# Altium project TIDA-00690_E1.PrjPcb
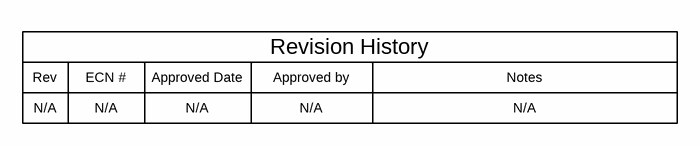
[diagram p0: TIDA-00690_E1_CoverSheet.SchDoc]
CopyrightYear: 2016; PCB_Layout: Who did the Layout?; PCB_Rev: E1; PRJ_Customer: Public Release; PRJ_Engineer: Enter name of project lead; PRJ_Number: TIDA-00690; PRJ_Title: Power for Wireless Switch; SCH_Rev: E1; TechSupport: http://www.ti.com/support; TID: TIDA-00690
2 sheets, 30 parts. Net scope: global (net labels, ports and power ports of the same name join across sheets).
Board file: TIDA-00690_E1_PCB.PcbDoc
Sheets:
  TIDA-00690_E1_CoverSheet.SchDoc
  TIDA-00690_E1_BlankSheet.SchDoc

## Sheet TIDA-00690_E1_CoverSheet.SchDoc
size 431 x 279 mm; Date: Not shown in title block; ApprovedBy: Not shown in title block; CheckedBy: Not shown in title block; Author: Not shown in title block; CompanyName: Not shown in title block; Engineer: Not shown in title block; Organization: Not shown in title block; Address1: Not shown in title block; Address2: Not shown in title block; Address3: Not shown in title block; Address4: Not shown in title block; DocumentNumber: 1; Revision: Use project parameter SCH_Rev; SheetNumber: 1; SheetTotal: 3; PageSetup: Record=PageOptions¦CenterHorizontal=True¦CenterVertical=True¦PrintScale=1.00¦XCorrection=1.00¦YCorrection=1.00¦PrintKind=0¦BorderSize=5000000¦LeftOffset=0¦BottomOffset=0¦Orientation=2¦PaperLength=1000¦PaperWidth=1000¦Scale=100¦PaperSource=15¦PrintQuality=600¦MediaType=1¦DitherType=10¦PaperKind=Letter¦PrintScaleMode=1

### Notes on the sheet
- Rev
- N/A
- ECN #
- Approved Date
- Approved by
- Revision History
- Notes

## Sheet TIDA-00690_E1_BlankSheet.SchDoc
size 431 x 279 mm; Date: Not shown in title block; ApprovedBy: Not shown in title block; CheckedBy: Not shown in title block; Author: Not shown in title block; CompanyName: Not shown in title block; Engineer: Not shown in title block; Organization: Not shown in title block; Address1: Not shown in title block; Address2: Not shown in title block; Address3: Not shown in title block; Address4: Not shown in title block; DocumentNumber: 1; Revision: Use project parameter SCH_Rev; SheetNumber: 2; SheetTotal: 3; PageSetup: Record=PageOptions¦CenterHorizontal=True¦CenterVertical=True¦PrintScale=1.00¦XCorrection=1.00¦YCorrection=1.00¦PrintKind=0¦BorderSize=5000000¦LeftOffset=0¦BottomOffset=0¦Orientation=2¦PaperLength=1000¦PaperWidth=1000¦Scale=100¦PaperSource=15¦PrintQuality=600¦MediaType=1¦DitherType=10¦PaperKind=Letter¦PrintScaleMode=1
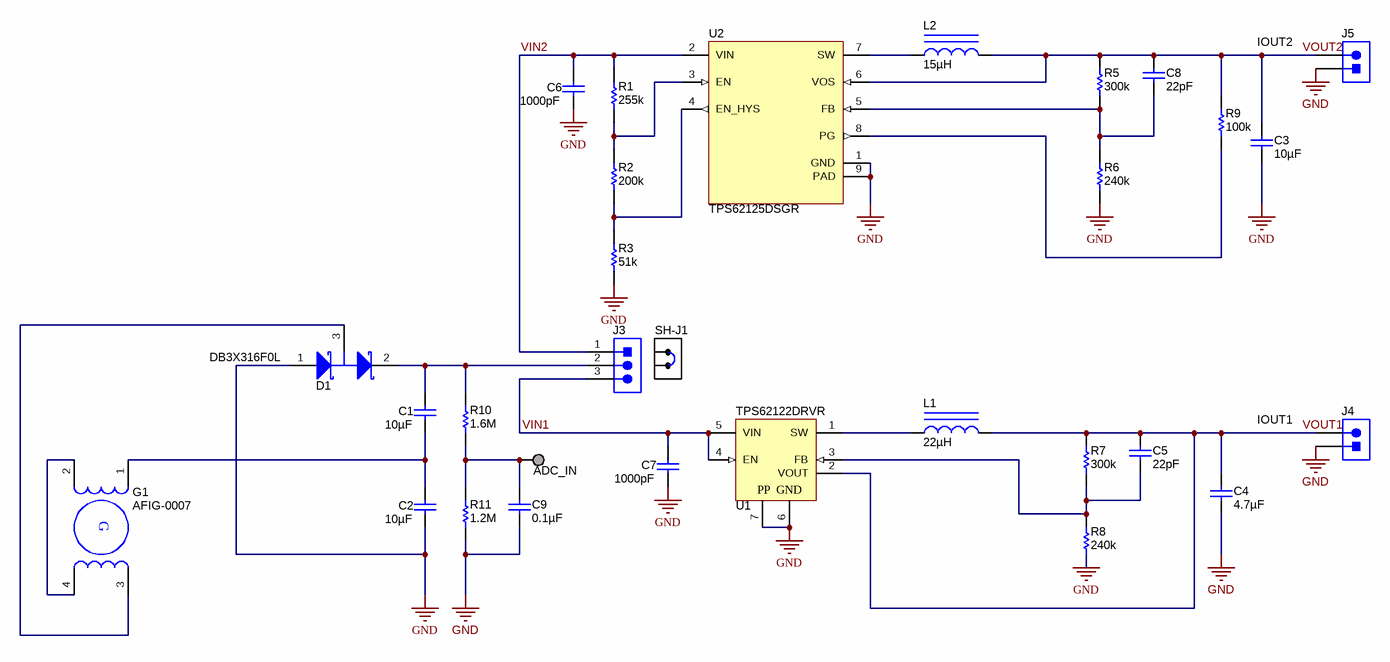
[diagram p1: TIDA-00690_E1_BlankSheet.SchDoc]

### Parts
ADC_IN  TESTPOINT  [TP_H045P075]  (value not drawn)  (no BOM)
C1  ValueDisplayed: 10µF  [0805_HV]  (hidden comment: GRM21BR61E106MA73)
C2  ValueDisplayed: 10µF  [0805_HV]  (hidden comment: GRM21BR61E106MA73)
C3  ValueDisplayed: 10µF  [0805_HV]  (hidden comment: GRM21BR61C106KE15L)
C4  ValueDisplayed: 4.7µF  [0603]  (hidden comment: GRM188R60J475KE19D)
C5  ValueDisplayed: 22pF  [0603]  (hidden comment: GRM1885C1H220JA01D)
C6  ValueDisplayed: 1000pF  [1206]  (hidden comment: GRM3195C1H102JA01D)
C7  ValueDisplayed: 1000pF  [1206]  (hidden comment: GRM3195C1H102JA01D)
C8  ValueDisplayed: 22pF  [0603]  (hidden comment: GRM1885C1H220JA01D)
C9  ValueDisplayed: 0.1µF  [0603]  (hidden comment: GRM188R71E104KA01D)
D1  DB3X316F0L  [SOT-23]
G1  AFIG-0007  [Cherry_AFIG-0007]
J3  61300311121  [WURTH_61300311121]  (value not drawn)
J4  61300211121  [WURTH_61300211121]  (value not drawn)
J5  61300211121  [WURTH_61300211121]  (value not drawn)
L1  ValueDisplayed: 22µH  [LQH3NP_G0]  (hidden comment: LQH3NPN220NG0)
L2  ValueDisplayed: 15µH  [LPS3314]  (hidden comment: LPS3314-153MLB)
R1  ValueDisplayed: 255k  [0603]  (hidden comment: CRCW0603255KFKEA)
R2  ValueDisplayed: 200k  [0603]  (hidden comment: CRCW0603200KFKEA)
R3  ValueDisplayed: 51k  [0603]  (hidden comment: RC0603JR-0751KL)
R5  ValueDisplayed: 300k  [0603]  (hidden comment: CRCW0603300KFKEA)
R6  ValueDisplayed: 240k  [0603]  (hidden comment: RC0603FR-07240KL)
R7  ValueDisplayed: 300k  [0603]  (hidden comment: CRCW0603300KFKEA)
R8  ValueDisplayed: 240k  [0603]  (hidden comment: RC0603FR-07240KL)
R9  ValueDisplayed: 100k  [0603]  (hidden comment: CRCW0603100KJNEA)
R10  ValueDisplayed: 1.6M  [0805_HV]  (hidden comment: CRCW08051M60JNEA)
R11  ValueDisplayed: 1.2M  [0805_HV]  (hidden comment: CRCW08051M20JNEA)
SH-J1  969102-0000-DA  [SNT-100-BK-G]  (value not drawn)
U1  TPS62122DRVR  [DRV0006A]
U2  TPS62125DSGR  [DSG0008A]

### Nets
GND: C2.2 C3.2 C4.2 C6.2 C7.2 C9.2 D1.1(A) J4.1 J5.1 R3.1 R6.1 R8.1 R11.1 U1.6(GND) U1.7(EP) U2.1(GND) U2.9(PAD)
VIN1: C7.1 J3.3 U1.4(EN) U1.5(VIN)
VIN2: C6.1 J3.1 R1.2 U2.2(VIN)
VOUT1: C4.1 C5.1 J4.2 L1.2 R7.2 U1.2(VOUT)
VOUT2: C3.1 C8.1 J5.2 L2.2 R5.2 R9.2 U2.6(VOS)
NetADC_IN_1: ADC_IN.1 C9.1 R10.1 R11.2
NetC1_1: C1.1 D1.2(K) J3.2 R10.2
NetC1_2: C1.2 C2.1 G1.1
NetC5_2: C5.2 R7.1 R8.2 U1.3(FB)
NetC8_2: C8.2 R5.1 R6.2 U2.5(FB)
NetD1_3: D1.3(C) G1.3
NetG1_2: G1.2 G1.4
NetL1_1: L1.1 U1.1(SW)
NetL2_1: L2.1 U2.7(SW)
NetR1_1: R1.1 R2.2 U2.3(EN)
NetR2_1: R2.1 R3.2 U2.4(EN_HYS)
NetR9_1: R9.1 U2.8(PG)

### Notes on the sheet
- IOUT2
- IOUT1

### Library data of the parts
ADC_IN = TP_H0.45P0.75: Manufacturer: Texas Instruments; CompType: Pad
C1 C2 = GRM21BR61E106MA73: CAP, CERM, 10 µF, 25 V, +/- 20%, X5R, 0805; Manufacturer: MuRata; Polarized: N; CompType: Capacitor; Value: 10uF; U/M: EA; Cap_F: 0.00001; Tolerance_%: 20; Value1: Unknown; VDC_V: 25; Value2: 25V; TaMin_C: -55; TaMax_C: 85; Cap_Case: 0805; SizeArea_mm2: 2.5; SizeAreaWB_mm2: 6.75; SizeX_mm: 2; SizeY_mm: 1.25; SizeZ_mm: 1.45; AEC Category: Q200
C3 = GRM21BR61C106KE15L: CAP, CERM, 10 µF, 16 V, +/- 10%, X5R, 0805; Manufacturer: MuRata; Polarized: N; CompType: Capacitor; Value: 10uF; U/M: EA; Cap_F: 0.00001; Tolerance_%: 10; ESR_ohm: 0.008; Value1: 0.008 ohm; VDC_V: 16; Value2: 16V; TaMin_C: -55; TaMax_C: 85; Cap_Case: 0805; SizeArea_mm2: 2.5; SizeAreaWB_mm2: 6.75; SizeX_mm: 2; SizeY_mm: 1.25; SizeZ_mm: 1.45; AEC Category: Q200
C4 = GRM188R60J475KE19D: CAP, CERM, 4.7 µF, 6.3 V, +/- 10%, X5R, 0603; Manufacturer: MuRata; Polarized: N; CompType: Capacitor; Value: 4.7uF; U/M: EA; Cap_F: 0.0000047; Tolerance_%: 10; ESR_ohm: 0.005; Value1: 0.005 ohm; VDC_V: 6.3; Value2: 6.3V; IRMS_A: 2; TaMin_C: -55; TaMax_C: 85; SizeArea_mm2: 1.28; SizeAreaWB_mm2: 4.68; SizeX_mm: 1.6; SizeY_mm: 0.8; SizeZ_mm: 1; AEC Category: Q200
C5 C8 = GRM1885C1H220JA01D: CAP, CERM, 22 pF, 50 V, +/- 5%, C0G/NP0, 0603; Manufacturer: MuRata; Polarized: N; CompType: Capacitor; Value: 22pF; U/M: EA; Cap_F: 0.000000000022; Tolerance_%: 5; Value1: Unknown; VDC_V: 50; Value2: 50V; TaMin_C: -55; TaMax_C: 125; SizeArea_mm2: 1.28; SizeAreaWB_mm2: 4.68; SizeX_mm: 1.6; SizeY_mm: 0.8; SizeZ_mm: 1; AEC Category: Q200
C6 C7 = GRM3195C1H102JA01D: CAP, CERM, 1000 pF, 50 V, +/- 5%, C0G/NP0, 1206; Manufacturer: MuRata; Polarized: N; CompType: Capacitor; Value: 1000pF; U/M: EA; Cap_F: 0.000000001; Tolerance_%: 5; Value1: Unknown; VDC_V: 50; Value2: 50V; TaMin_C: -55; TaMax_C: 125; SizeArea_mm2: 5.12; SizeAreaWB_mm2: 10.92; SizeX_mm: 3.2; SizeY_mm: 1.6; SizeZ_mm: 1.35; AEC Category: Q200
C9 = GRM188R71E104KA01D: CAP, CERM, 0.1 µF, 25 V, +/- 10%, X7R, 0603; Manufacturer: MuRata; Polarized: N; CompType: Capacitor; Value: 0.1uF; U/M: EA; Cap_F: 0.0000001; Tolerance_%: 10; Value1: Unknown; VDC_V: 25; Value2: 25V; TaMin_C: -55; TaMax_C: 125; SizeArea_mm2: 1.28; SizeAreaWB_mm2: 4.68; SizeX_mm: 1.6; SizeY_mm: 0.8; SizeZ_mm: 1; AEC Category: Q200
D1 = DB3X316F0L: Diode, Schottky, 30 V, 0.1 A, SOT-23; Manufacturer: Panasonic; SymbolCreator: Altium; U/M: EA; Vf_V: 0.55; Value: 30V; Value1: 0.1A; Value2: 0.55V; Io_A: 0.1; Vr_V: 30; TJmax_C: 125
G1 = AFIG-0007: AC generator, Through-hole mount; Manufacturer: Cherry Switch; SymbolCreator: Altium
J3 = 61300311121: Header, 2.54 mm, 3x1, Gold, TH; Manufacturer: Wurth Elektronik; SymbolCreator: a0799628
J4 J5 = 61300211121: Header, 2.54 mm, 2x1, Gold, TH; Manufacturer: Wurth Elektronik eiSos; SymbolCreator: a0412235; U/M: EA
L1 = LQH3NPN220NG0: Inductor, Wirewound, Ferrite, 22 µH, 0.34 A, 1.1 ohm, SMD; Manufacturer: MuRata; Value: 22uH; Ind_H: 22.0E-6; Imax_A: 0.34; Irms: 0.43A @ 40C rise; Isat: 0.34A @ 30% inductance drop; DCR_ohm: 1.1; Value1: 1.1 ohm; Value2: 0.34A; AEC Category: Q200
L2 = LPS3314-153MLB: Inductor, Shielded Drum Core, Ferrite, 15 µH, 0.59 A, 0.44 ohm, SMD; Manufacturer: Coilcraft; Value: 15uH; Ind_H: 15.0E-6; Imax_A: 0.59; Irms: 0.82A @ 40C rise; Isat: 0.59A @ 30% inductance drop; DCR_ohm: 0.44; Value2: 0.59A; AEC Category: Q200
R1 = CRCW0603255KFKEA: RES, 255 k, 1%, 0.1 W, 0603; Manufacturer: Vishay-Dale; CompType: Resistor; Value: 255k; Res_ohm: 255000; Tolerance_%: 1; Power_W: 0.1; Value2: 0.1W; VDC_V: 75; TempCo: 100 ppm/C; SizeArea_mm2: 1.28; SizeX_mm: 1.6; SizeY_mm: 0.8; EIA_Code: E96; U/M: EA; AEC Category: Q200
R2 = CRCW0603200KFKEA: RES, 200 k, 1%, 0.1 W, 0603; Manufacturer: Vishay-Dale; CompType: Resistor; Value: 200k; Res_ohm: 200000; Tolerance_%: 1; Power_W: 0.1; Value2: 0.1W; VDC_V: 75; TempCo: 100 ppm/C; SizeArea_mm2: 1.28; SizeX_mm: 1.6; SizeY_mm: 0.8; EIA_Code: E96; U/M: EA; AEC Category: Q200
R3 = RC0603JR-0751KL: RES, 51 k, 5%, 0.1 W, 0603; Manufacturer: Yageo America; CompType: Resistor; Value: 51k; Res_ohm: 51000; Value_Code: 51k0; Tolerance_%: 5; Power_W: 0.1; Value2: 0.1W; VDC_V: 50; TempCo: 100 ppm/C; SizeArea_mm2: 1.28; SizeX_mm: 1.6; SizeY_mm: 0.8; SizeZ_mm: 1; EIA_Code: E24; U/M: EA; AEC Category: Q200
R5 R7 = CRCW0603300KFKEA: RES, 300 k, 1%, 0.1 W, 0603; Manufacturer: Vishay-Dale; CompType: Resistor; Value: 300k; Res_ohm: 300000; Tolerance_%: 1; Power_W: 0.1; Value2: 0.1W; TempCo: 100 ppm/C; SizeArea_mm2: 1.28; SizeX_mm: 1.6; SizeY_mm: 0.8; U/M: EA; AEC Category: Q200
R6 R8 = RC0603FR-07240KL: RES, 240 k, 1%, 0.1 W, 0603; Manufacturer: Yageo America; CompType: Resistor; Value: 240k; Res_ohm: 240000; Tolerance_%: 1; Power_W: 0.1; Value2: 0.1W; VDC_V: 150; TempCo: 200 ppm/C; SizeArea_mm2: 1.28; SizeX_mm: 1.6; SizeY_mm: 0.8; U/M: EA; AEC Category: Q200
R9 = CRCW0603100KJNEA: RES, 100 k, 5%, 0.1 W, 0603; Manufacturer: Vishay-Dale; CompType: Resistor; Value: 100k; Res_ohm: 100000; Tolerance_%: 5; Power_W: 0.1; Value2: 0.1W; VDC_V: 75; TempCo: 200 ppm/C; SizeArea_mm2: 1.28; SizeX_mm: 1.6; SizeY_mm: 0.8; SizeZ_mm: 1; EIA_Code: E24; U/M: EA; AEC Category: Q200
R10 = CRCW08051M60JNEA: RES, 1.6 M, 5%, 0.125 W, 0805; Manufacturer: Vishay-Dale; CompType: Resistor; Value: 1.6Meg; Res_ohm: 1600000; Value_Code: 1M60; Tolerance_%: 5; Power_W: 0.125; Value2: 0.125W; VDC_V: 150; TempCo: 200 ppm/C; SizeArea_mm2: 2.5; SizeX_mm: 2; SizeY_mm: 1.25; SizeZ_mm: 1.45; EIA_Code: E24; U/M: EA; AEC Category: Q200
R11 = CRCW08051M20JNEA: RES, 1.2 M, 5%, 0.125 W, 0805; Manufacturer: Vishay-Dale; CompType: Resistor; Value: 1.2Meg; Res_ohm: 1200000; Value_Code: 1M20; Tolerance_%: 5; Power_W: 0.125; Value2: 0.125W; VDC_V: 150; TempCo: 200 ppm/C; SizeArea_mm2: 2.5; SizeX_mm: 2; SizeY_mm: 1.25; SizeZ_mm: 1.45; EIA_Code: E24; U/M: EA; AEC Category: Q200
SH-J1 = 969102-0000-DA: Shunt, 100mil, Gold plated, Black; Manufacturer: 3M; Alternate Manufacturer: Samtec; Value: 1x2; Note: You can "mate" this to a header by matching the designator.  i.e. use SH-J3 for header J3
U1 = TPS62122DRVR: Buck Step Down Regulator with 2 to 15 V Input and 1.2 to 5.5 V Output, -40 to 85 degC, 6-Pin SON (DRV), Green (RoHS & no Sb/Br); Manufacturer: Texas Instruments; Alternate Manufacturer: None; Alternate PartNumber: Equivalent; Duty Cycle(Max)(%): 100; Iout(Max)(A): 0.075; Iq(Typ)(mA): 0.011; Rating: Catalog; Regulated Outputs(#): 1; SubFamily: Step-Down Regulator; Switch Current Limit(Typ)(A): 0.25; Synchronous Rectification: TRUE; Vin(Max)(V): 15; Vin(Min)(V): 2; Vout(Max)(V): 5.5; Vout(Min)(V): 1.2
U2 = TPS62125DSGR: 3V-17V, 300mA Step Down Converter With Adjustable Enable Threshold And Hysteresis, DSG0008A; Alternate PartNumber: TPS62125DSGT; Manufacturer: Texas Instruments; SymbolCreator: a0412235; CompType: IC; U/M: EA

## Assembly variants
001: not fitted FID1 FID2 FID3 H1 H2 H3 H4 H5 H6 H7 H8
